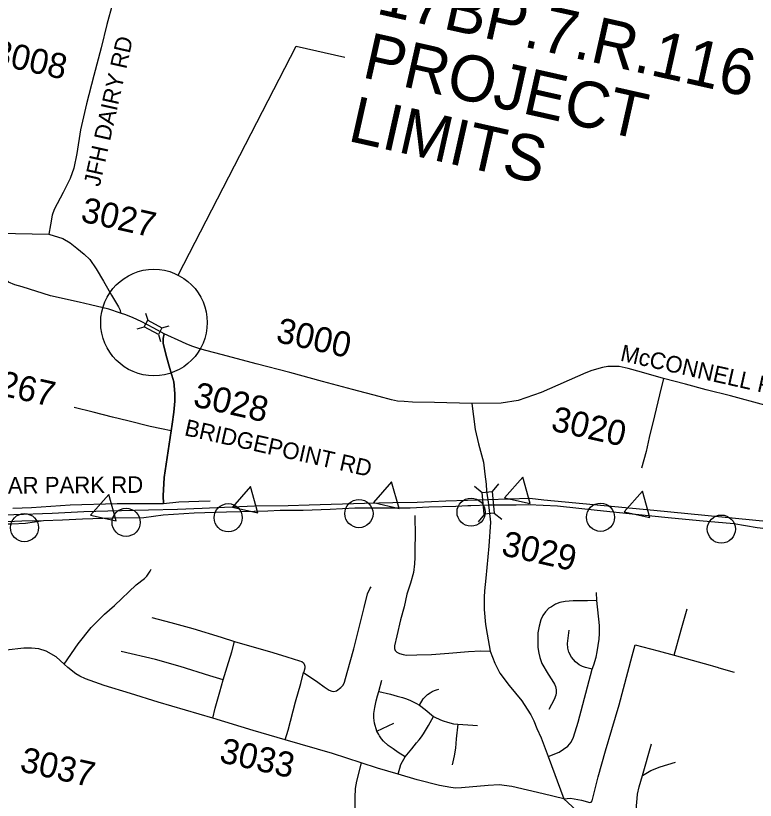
# Model space of a CAD drawing. Extents: x 1784499 to 1786147, y 841097 to 842538.
# Drawn here: x 1784767.1 to 1784963.4, y 842114.2 to 842322.5 of the extents above; entities that cross this region are included whole.
import ezdxf

# ---------------------------------------------------------------- set-up
doc = ezdxf.new("R2010")
doc.units = 0
for name, color, linetype in [('DEV CONE PLAN VIEW CELL', 7, 'Continuous'), ('Exist Road Primary Interstate Divided Center Attributed', 7, 'Continuous'), ('Exist Road Primary Interstate Ramp 1 Lane Attributed', 7, 'Continuous'), ('Exist Road Primary Interstate Service Attributed', 7, 'Continuous'), ('Exist Road Secondary Structure Standard Bridge CELL', 7, 'Continuous'), ('Exist Road Secondary Type 41 Attributed', 7, 'Continuous'), ('Exist Road Secondary Type 51 Attributed', 7, 'Continuous'), ('Exist Road Secondary Type 51 Number Label', 7, 'Continuous'), ('Old_Level_40', 7, 'Continuous'), ('Prop DSN Text', 7, 'Continuous'), ('Scratch_Level_3', 7, 'Continuous')]:
    doc.layers.add(name, color=color, linetype=linetype)

msp = doc.modelspace()

# ---------------------------------------------------------------- linework, layer by layer
at = {"layer": 'DEV CONE PLAN VIEW CELL'}
for points in [[(1784901.69, 842200), (1784896.89, 842194.51), (1784903.69, 842192.99)], [(1784829.4, 842197.52), (1784824.61, 842192.04), (1784831.41, 842190.51)], [(1784866.88, 842198.71), (1784862.08, 842193.22), (1784868.88, 842191.7)], [(1784791.79, 842195.41), (1784786.99, 842189.93), (1784793.79, 842188.4)], [(1784933.46, 842196.27), (1784928.66, 842190.79), (1784935.46, 842189.26)]]:
    msp.add_lwpolyline(points, close=True, dxfattribs=at)
for centre in [(1784823.5, 842189.22), (1784858.21, 842190.31), (1784887.99, 842190.69), (1784922.35, 842189.34), (1784796.41, 842187.99), (1784769.42, 842186.58), (1784954.43, 842186.19)]:
    msp.add_circle(centre, 3.74, dxfattribs=at)
at = {"layer": 'Exist Road Primary Interstate Divided Center Attributed'}
for points in [[(1784892.4, 842193.99), (1784887.07, 842193.79), (1784881.29, 842193.62), (1784873.67, 842193.29), (1784867.2, 842193.21), (1784859.72, 842193.02), (1784844.96, 842192.54), (1784839.42, 842192.34), (1784830.45, 842192.32), (1784816.61, 842191.67), (1784810.04, 842191.4), (1784802.34, 842191.25), (1784791.56, 842190.92), (1784785.16, 842190.77), (1784776.81, 842190.33), (1784766.61, 842190.01), (1784755.84, 842189.9), (1784753.05, 842189.8)], [(1784980.73, 842186.78), (1784936.5, 842191.15), (1784907.31, 842193.9), (1784903.59, 842194.28), (1784892.4, 842193.99)], [(1784774.51, 842188.49), (1784779.53, 842188.67), (1784784.86, 842188.92), (1784793, 842189.15), (1784801.13, 842189.24), (1784806.23, 842189.95), (1784814.46, 842190.47), (1784823.07, 842190.78), (1784834.07, 842191.01), (1784837.32, 842191.18), (1784843.39, 842191.2), (1784850.61, 842191.53), (1784857.16, 842191.81), (1784863.95, 842191.87), (1784871.85, 842191.86), (1784876.81, 842192.08), (1784883.96, 842192.3), (1784887.13, 842192.43), (1784887.93, 842192.47), (1784892.58, 842192.67)], [(1784892.58, 842192.67), (1784899.97, 842192.68), (1784903.35, 842192.69), (1784910.9, 842192.36), (1784921.42, 842191.2), (1784931.61, 842190.14), (1784940.34, 842189.28), (1784948.6, 842188.51), (1784957.77, 842187.67), (1784963.9, 842186.64), (1784970.81, 842185.8), (1784978.25, 842185.25), (1784985.05, 842184.39), (1784988.3, 842184.13), (1784991.42, 842183.79), (1784995.13, 842183.43), (1784996.87, 842183.27)], [(1784728.39, 842187.12), (1784729.7, 842187.19), (1784739.5, 842187.38), (1784754.22, 842187.95), (1784764.82, 842188.17), (1784768.7, 842188.39), (1784774.51, 842188.49)]]:
    msp.add_lwpolyline(points, dxfattribs=at)
at = {"layer": 'Exist Road Primary Interstate Ramp 1 Lane Attributed'}
msp.add_lwpolyline([(1784736.82, 842178), (1784746.26, 842182.07), (1784751.88, 842184.57), (1784756.13, 842186.14), (1784759.12, 842186.92), (1784761.51, 842187.25), (1784763.74, 842187.55), (1784766.07, 842187.6), (1784769.73, 842187.8), (1784774.51, 842188.49)], dxfattribs=at)
at = {"layer": 'Exist Road Primary Interstate Service Attributed'}
msp.add_lwpolyline([(1784806.33, 842192.98), (1784810.37, 842193.39), (1784815.71, 842193.62), (1784818.68, 842193.72)], dxfattribs=at)
at = {"layer": 'Exist Road Secondary Structure Standard Bridge CELL'}
for p, q in [((1784801.58, 842243.55), (1784802.14, 842241.67)), ((1784799.3, 842239.34), (1784801.18, 842239.9)), ((1784805.92, 842239.62), (1784807.8, 842240.18)), ((1784804.99, 842237.89), (1784805.55, 842236)), ((1784888.89, 842197.55), (1784890.91, 842195.89)), ((1784895.24, 842198.19), (1784893.58, 842196.16)), ((1784891.53, 842190.19), (1784889.87, 842188.16)), ((1784894.14, 842190.45), (1784896.16, 842188.79))]:
    msp.add_line(p, q, dxfattribs=at)
for points in [[(1784802.14, 842241.67), (1784805.92, 842239.62), (1784804.97, 842237.86), (1784801.18, 842239.9)], [(1784893.58, 842196.16), (1784894.15, 842190.45), (1784891.48, 842190.18), (1784890.91, 842195.89)]]:
    msp.add_lwpolyline(points, close=True, dxfattribs=at)
at = {"layer": 'Exist Road Secondary Type 41 Attributed'}
msp.add_lwpolyline([(1784939.07, 842226.2), (1784937.97, 842221.87), (1784936.66, 842216.23), (1784935.31, 842210.51), (1784934.48, 842206.77), (1784933.26, 842202.34)], dxfattribs=at)
at = {"layer": 'Exist Road Secondary Type 51 Attributed'}
for p, q in [((1784863, 842132.59), (1784867.52, 842134.64)), ((1784933.5, 842120.76), (1784935.87, 842129.18))]:
    msp.add_line(p, q, dxfattribs=at)
for points in [[(1784787.81, 842335.88), (1784789.61, 842335.61), (1784791.47, 842335.23), (1784792.38, 842334.99), (1784792.91, 842334.77), (1784793.45, 842334.43), (1784793.9, 842334), (1784794.16, 842333.56), (1784794.27, 842332.96), (1784794.01, 842331.03), (1784792.79, 842325.62), (1784791.25, 842320.11), (1784789.8, 842313.98), (1784787.86, 842306.62), (1784785.91, 842299.11), (1784784.3, 842292.16), (1784783.32, 842285.88), (1784782.51, 842281.97), (1784781.55, 842279.27), (1784779.73, 842275.55), (1784777.3, 842271.04), (1784776.75, 842269.5), (1784776.34, 842266.99), (1784775.93, 842264.5)], [(1784749.29, 842263.86), (1784751.48, 842264.77), (1784753.64, 842265.08), (1784759.28, 842264.91), (1784767, 842264.67), (1784775.93, 842264.5)], [(1784794.94, 842243.56), (1784791.78, 842244.55), (1784786.93, 842245.7), (1784783.91, 842246.47), (1784776.37, 842248.16), (1784768.77, 842250.47), (1784766.86, 842251), (1784765.2, 842251.78), (1784762.35, 842254.04), (1784756.81, 842258.33), (1784752.52, 842261.5), (1784749.29, 842263.86)], [(1784775.93, 842264.5), (1784779.62, 842263.34), (1784781.55, 842262.2), (1784783.33, 842260.81), (1784785.26, 842259.18), (1784786.73, 842257.76), (1784788.47, 842255.28), (1784790.44, 842252.05), (1784792.49, 842248.3), (1784794.4, 842245.2), (1784794.8, 842244.34), (1784794.94, 842243.56)], [(1784803.74, 842239.56), (1784800.4, 842241.32), (1784798.3, 842242.3), (1784796.33, 842243.08), (1784794.94, 842243.56)], [(1784806.51, 842238.06), (1784803.74, 842239.56)], [(1784806.51, 842238.06), (1784806.25, 842236.75), (1784806.26, 842235.57), (1784807.07, 842232.28), (1784807.97, 842228.86), (1784809.04, 842225.32), (1784809.36, 842222.2), (1784809.34, 842220.15), (1784809.07, 842217.28), (1784808.67, 842214.03), (1784808.35, 842212.31)], [(1784888.16, 842219.56), (1784878.3, 842219.82), (1784872.46, 842219.92), (1784870.19, 842220.05), (1784868.44, 842220.15), (1784866.85, 842220.51), (1784863.62, 842221.36), (1784856.54, 842223.25), (1784848.55, 842225.41), (1784839.83, 842227.75), (1784830.93, 842230.09), (1784823.34, 842232.09), (1784816.26, 842233.98), (1784814.11, 842234.69), (1784812.54, 842235.3), (1784811.2, 842235.87), (1784806.51, 842238.06)], [(1784939.07, 842226.2), (1784933.23, 842227.83), (1784929.71, 842228.82), (1784927.32, 842229.34), (1784925.86, 842229.38), (1784924.25, 842229.37), (1784922.86, 842229.13), (1784920.02, 842228.3), (1784918.43, 842227.65), (1784906.57, 842222.42), (1784900.52, 842220.3), (1784895.94, 842219.64), (1784888.16, 842219.56)], [(1784981.23, 842214.77), (1784978.04, 842215.71), (1784971.85, 842217.46), (1784965.96, 842219.11), (1784956.88, 842221.58), (1784950.36, 842223.17), (1784944.92, 842224.66), (1784939.07, 842226.2)], [(1784808.35, 842212.31), (1784805.82, 842212.78), (1784802.8, 842213.45), (1784796.85, 842214.91), (1784792.78, 842215.95), (1784787.64, 842217.23), (1784782.57, 842218.49)], [(1784888.16, 842219.56), (1784889.08, 842212.65), (1784889.99, 842208.81), (1784891.26, 842203.92), (1784891.62, 842200.79), (1784891.98, 842198.08), (1784892.1, 842196.24), (1784892.4, 842193.99)], [(1784808.35, 842212.31), (1784807.3, 842205.22), (1784806.47, 842199.86), (1784806.22, 842194.99), (1784806.33, 842192.98)], [(1784892.4, 842193.99), (1784892.49, 842193.31), (1784892.58, 842192.67)], [(1784892.58, 842192.67), (1784892.77, 842191.15), (1784893.13, 842188.04)], [(1784873.06, 842189.78), (1784873.13, 842184.35), (1784873.07, 842181.39), (1784873.07, 842178.68), (1784872.96, 842176.97), (1784872.66, 842174.71), (1784871.94, 842171.82), (1784870.97, 842168.91), (1784870.22, 842165.59), (1784869.29, 842162.12), (1784868.27, 842157.88), (1784867.68, 842155.24), (1784867.66, 842154.9), (1784867.7, 842154.52), (1784867.77, 842154.22), (1784867.87, 842153.97), (1784868.01, 842153.76), (1784868.27, 842153.53), (1784868.61, 842153.32), (1784868.98, 842153.18), (1784869.95, 842152.93), (1784870.85, 842152.76), (1784873.58, 842152.83), (1784877.46, 842152.91), (1784882.05, 842153.24), (1784887.27, 842153.66), (1784890.62, 842153.88), (1784893.08, 842153.81)], [(1784893.13, 842188.04), (1784892.72, 842181.68), (1784891.91, 842173.18), (1784891.59, 842169.81), (1784891.44, 842168.15), (1784891.47, 842164.87), (1784891.83, 842160.91), (1784892.23, 842158.3), (1784893.08, 842153.81)], [(1784780, 842150.37), (1784783.65, 842155.73), (1784787.15, 842160.07), (1784788.97, 842161.94), (1784790.64, 842163.65), (1784793.35, 842165.93), (1784799.1, 842171.37), (1784801.29, 842173.08), (1784801.91, 842173.73), (1784802.78, 842174.99), (1784803.08, 842175.53)], [(1784843.54, 842148.17), (1784847.27, 842145.53), (1784848.97, 842144.28), (1784850.27, 842143.46), (1784851.01, 842143.14), (1784851.57, 842143.05), (1784852.25, 842143.24), (1784853.4, 842144.11), (1784854, 842144.8), (1784854.34, 842145.57), (1784855.1, 842148.13), (1784856.89, 842154.39), (1784859.59, 842165.4), (1784860.51, 842168.98), (1784861.14, 842170.3), (1784861.5, 842170.9)], [(1784921.4, 842167.2), (1784921.32, 842169.39)], [(1784921.4, 842167.2), (1784918.91, 842167.15), (1784916.79, 842167.12), (1784915.12, 842167.11), (1784913, 842166.98), (1784911.54, 842166.7), (1784910.38, 842166.26), (1784909.33, 842165.6), (1784908.63, 842165.19), (1784907.78, 842164.26), (1784907.05, 842163.28), (1784906.5, 842162.09), (1784906.07, 842160.44), (1784905.73, 842158.66), (1784905.67, 842156.99), (1784905.68, 842154.72), (1784905.96, 842153.25), (1784906.2, 842152.12), (1784906.77, 842150.5), (1784908.43, 842147.69), (1784909.46, 842146.19), (1784910.1, 842145.04), (1784910.4, 842144.39), (1784910.56, 842143.54), (1784910.57, 842142.71), (1784910.46, 842142.15), (1784910.06, 842140.98), (1784908.62, 842138.33)], [(1784920.17, 842149.05), (1784920.58, 842150.13), (1784921.2, 842152.2), (1784921.42, 842153.61), (1784921.97, 842157), (1784922.08, 842158.5), (1784922.1, 842160.57), (1784921.4, 842167.2)], [(1784941.89, 842152.72), (1784943.78, 842159.44), (1784945.39, 842165.04)], [(1784803.19, 842162.77), (1784808.24, 842161.36), (1784814.08, 842159.78), (1784821.63, 842157.54), (1784825.19, 842156.39)], [(1784920.17, 842149.05), (1784918.38, 842149.45), (1784917.59, 842149.75), (1784916.69, 842150.18), (1784915.75, 842150.97), (1784915.22, 842151.56), (1784914.64, 842152.23), (1784913.93, 842153.48), (1784913.67, 842154.59), (1784913.62, 842155.81), (1784913.72, 842157.25), (1784914.04, 842159.38)], [(1784780, 842150.37), (1784777.8, 842152.27), (1784775.22, 842153.83), (1784773.25, 842154.41), (1784771.32, 842154.57), (1784769.22, 842154.55), (1784764.56, 842154.05), (1784761.96, 842154.01), (1784759.71, 842154.3), (1784753.8, 842155.56)], [(1784822.2, 842146.21), (1784823.23, 842149.61), (1784824.44, 842153.58), (1784825.19, 842156.39)], [(1784825.19, 842156.39), (1784835.33, 842153.42), (1784839.08, 842152.25), (1784842.42, 842151.23), (1784843.08, 842151.03), (1784843.51, 842150.71), (1784843.65, 842150.35), (1784843.86, 842149.81), (1784843.84, 842149.27), (1784843.57, 842148.29), (1784843.54, 842148.17)], [(1784912.65, 842114.61), (1784914.35, 842114.77), (1784917.28, 842114.21), (1784919.52, 842113.64), (1784919.88, 842113.72), (1784920.16, 842114.07), (1784921.76, 842120.45), (1784923.71, 842127.29), (1784925.34, 842133.03), (1784927.31, 842139.53), (1784930.73, 842152.55), (1784931.59, 842155.5)], [(1784931.59, 842155.5), (1784937.66, 842153.86), (1784941.89, 842152.72)], [(1784822.2, 842146.21), (1784818.63, 842147.28), (1784810.78, 842149.74), (1784804.17, 842151.54), (1784795.09, 842153.73)], [(1784893.08, 842153.81), (1784894.26, 842150.63), (1784895.64, 842147.99), (1784898.12, 842144.65), (1784901.43, 842140.6), (1784902.9, 842138.38), (1784903.83, 842136.92), (1784904.64, 842135.31), (1784905.48, 842133.25), (1784906.58, 842130.8), (1784908.46, 842125.82)], [(1784941.89, 842152.72), (1784951.49, 842150.03), (1784952.04, 842149.87), (1784953.59, 842149.44), (1784953.75, 842149.39), (1784957.87, 842148.18)], [(1784819.39, 842136.03), (1784804.87, 842140.26), (1784797.57, 842142.55), (1784790.61, 842144.65), (1784785.61, 842146.42), (1784784.11, 842147.11), (1784783.07, 842147.76), (1784780.95, 842149.42), (1784780, 842150.37)], [(1784841.35, 842140.34), (1784842.82, 842145.22), (1784843.54, 842148.17)], [(1784908.46, 842125.82), (1784911.33, 842126.99), (1784912.56, 842127.77), (1784913.64, 842128.58), (1784914.58, 842129.64), (1784915.22, 842130.96), (1784916.38, 842134.91), (1784920.17, 842149.05)], [(1784819.39, 842136.03), (1784820.08, 842138.68), (1784821.32, 842142.96), (1784822.2, 842146.21)], [(1784863.47, 842143.12), (1784864.29, 842146.13)], [(1784863, 842132.59), (1784862.34, 842134.64), (1784862.17, 842136.09), (1784862.2, 842137.28), (1784862.43, 842138.86), (1784862.8, 842140.58), (1784863.14, 842141.92), (1784863.47, 842143.12)], [(1784863.47, 842143.12), (1784866.59, 842142.38), (1784868.39, 842141.88), (1784869.74, 842141.49), (1784870.81, 842141.11), (1784871.88, 842140.68), (1784873.29, 842139.95), (1784874.25, 842139.45)], [(1784874.25, 842139.45), (1784875.3, 842141.11), (1784875.85, 842141.75), (1784876.41, 842142.28), (1784877.11, 842142.75), (1784877.69, 842143.04), (1784878.32, 842143.32), (1784878.84, 842143.53), (1784879.44, 842143.74)], [(1784838.59, 842130.28), (1784839.41, 842132.85), (1784841.35, 842140.34)], [(1784874.25, 842139.45), (1784875.81, 842138.32), (1784878.04, 842136.47)], [(1784838.59, 842130.28), (1784830.16, 842132.73), (1784819.39, 842136.03)], [(1784870.48, 842125.73), (1784872.26, 842127.88), (1784873.53, 842129.43), (1784874.21, 842130.27), (1784874.81, 842131.05), (1784875.38, 842131.86), (1784875.89, 842132.69), (1784876.72, 842134.08), (1784878.04, 842136.47)], [(1784878.04, 842136.47), (1784878.7, 842136.12), (1784879.33, 842135.84), (1784879.9, 842135.6), (1784880.6, 842135.31), (1784881.69, 842134.91), (1784883.29, 842134.51), (1784884.51, 842134.4)], [(1784870.48, 842125.73), (1784868.67, 842126.88), (1784867.29, 842127.85), (1784866.01, 842128.75), (1784864.77, 842129.87), (1784864.22, 842130.55), (1784863.7, 842131.32), (1784863.46, 842131.7), (1784863, 842132.59)], [(1784884.51, 842134.4), (1784884.04, 842130.53), (1784883.87, 842128.01), (1784883.47, 842126.01), (1784882.94, 842123.65)], [(1784884.51, 842134.4), (1784888.49, 842134.1), (1784889.72, 842134.07)], [(1784858.84, 842124.15), (1784851.21, 842126.61), (1784838.59, 842130.28)], [(1784868.6, 842121.12), (1784869.37, 842123.67), (1784869.79, 842124.53), (1784870.48, 842125.73)], [(1784908.46, 842125.82), (1784912.65, 842114.61)], [(1784933.5, 842120.76), (1784935.67, 842122.09), (1784938.19, 842123.09), (1784942.29, 842124.35)], [(1784858.84, 842124.15), (1784857.58, 842119.32), (1784857.25, 842117.35), (1784857.15, 842114.91), (1784857.13, 842112.67), (1784857.32, 842110.08)], [(1784868.6, 842121.12), (1784863.12, 842122.77), (1784858.84, 842124.15)], [(1784912.65, 842114.61), (1784907.14, 842115.91), (1784898.83, 842117.85), (1784895.48, 842118.28), (1784892.55, 842118.15), (1784885.42, 842117.55), (1784883.89, 842117.46), (1784882.64, 842117.62), (1784879.57, 842118.14), (1784873.63, 842119.61), (1784868.6, 842121.12)], [(1784931.84, 842109.88), (1784931.93, 842112.7), (1784932.07, 842114.67), (1784932.2, 842115.79), (1784932.64, 842117.74), (1784933.5, 842120.76)], [(1784912.65, 842114.61), (1784919.26, 842108.5), (1784923.63, 842104.7), (1784925.93, 842102.29)]]:
    msp.add_lwpolyline(points, dxfattribs=at)
at = {"layer": 'Old_Level_40'}
for p, q in [((1784810.26, 842253.61), (1784841.55, 842314.42)), ((1784841.55, 842314.42), (1784854.45, 842311.52))]:
    msp.add_line(p, q, dxfattribs=at)
msp.add_circle((1784803.79, 842241.04), 14.14, dxfattribs=at)
at = {"layer": 'Scratch_Level_3'}
msp.add_lwpolyline([(1784766.37, 842191.76), (1784771.29, 842191.91), (1784781.56, 842192.63), (1784794.04, 842192.98), (1784806.33, 842192.98), (1784806.22, 842194.99), (1784806.47, 842199.86), (1784807.3, 842205.22), (1784808.35, 842212.31), (1784808.67, 842214.03), (1784809.07, 842217.28), (1784809.34, 842220.15), (1784809.36, 842222.2), (1784809.04, 842225.32), (1784807.97, 842228.86), (1784807.07, 842232.28), (1784806.26, 842235.57), (1784806.25, 842236.75), (1784806.51, 842238.06)], dxfattribs=at)

# ---------------------------------------------------------------- texts
at = {"layer": 'Exist Road Secondary Type 51 Number Label'}
for s, p in [('3008', (1784760.52, 842309.83)), ('3027', (1784784.08, 842267.91)), ('3000', (1784835.92, 842235.93)), ('3267', (1784757.37, 842222.95)), ('3028', (1784813.93, 842218.85)), ('3020', (1784908.92, 842212.42)), ('3029', (1784895.75, 842179.34)), ('3033', (1784820.89, 842124.39)), ('3037', (1784767.92, 842121.95))]:
    msp.add_text(s, height=6.665, rotation=347.3599, dxfattribs=at).set_placement(p)
at = {"layer": 'Old_Level_40'}
for s, height, p in [('17BP.7.R.116', 12.2195, (1784862.52, 842323.1)), ('PROJECT', 12.219, (1784858.73, 842306.21)), ('LIMITS', 12.219, (1784854.95, 842289.32))]:
    msp.add_text(s, height=height, rotation=347.3599, dxfattribs=at).set_placement(p)
at = {"layer": 'Prop DSN Text'}
for s, rotation, p in [('JFH DAIRY RD', 77.336, (1784789.39, 842276.92)), ('McCONNELL RD', 347.336, (1784927.38, 842230.95)), ('BRIDGEPOINT RD', 347.336, (1784811.66, 842211.14)), ('CEDAR PARK RD', 0.3625, (1784752.6, 842195.52))]:
    msp.add_text(s, height=4.3971, rotation=rotation, dxfattribs=at).set_placement(p)

doc.saveas('drawing.dxf')
